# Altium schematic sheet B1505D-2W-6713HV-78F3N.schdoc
size 277 x 190 mm; Device: default297x210; Symbol: default297x210; Name: default297x210; Date: 2025.07.09; Rev: V1.1; Size: "A4"; Id: /; File: B1505D-2W-6713HV-78F3N; Sheet: /; @Page No: 1; @Page Count: 1; @Schematic Name: B1505D-2W-6713HV-78F3N; @Project Name: 全桥隔离电源-B1505D-2W-6713HV-78F3N; @Board Name: B1505D-2W-6713HV-78F3N; @Update Date: 2025-07-09; @Create Time: 17:16:26; @Update Time: 09:23:58; @Page Name: B1505D-2W-6713HV-78F3N; @Create Date: 2025-07-08
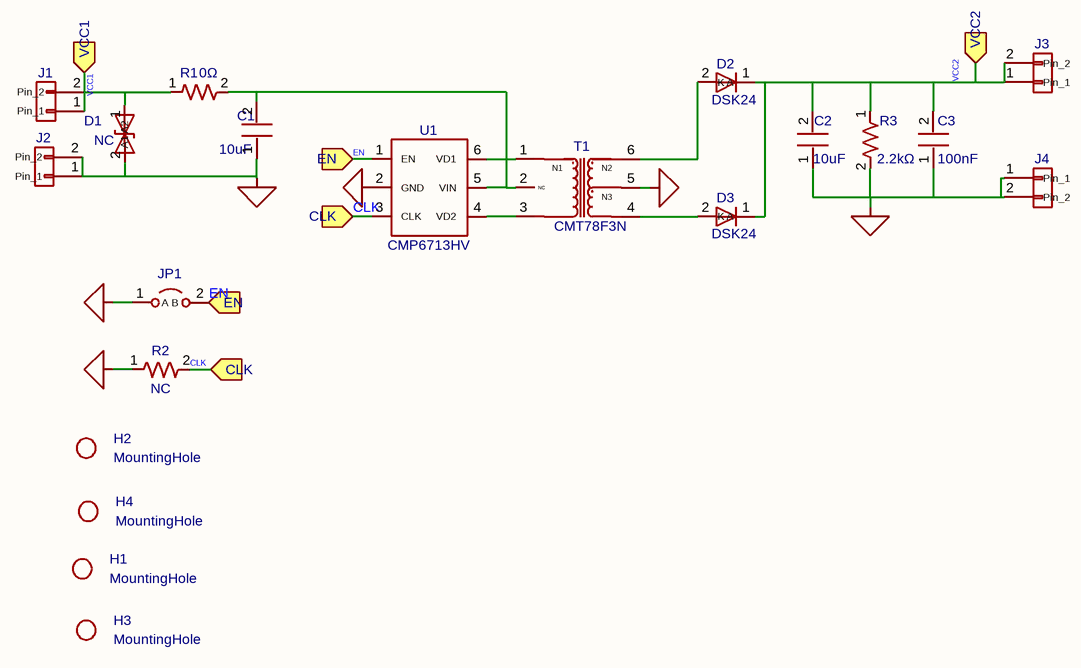
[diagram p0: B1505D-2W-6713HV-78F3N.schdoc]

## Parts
C1  10uF  [C0805]
C2  10uF  [C0805]
C3  100nF  [C0603]
D1  value NC  [SOD-123FL_L2.8-W1.8-LS3.7-BI]
D2  DSK24  [SOD-123_L2.8-W1.8-LS3.7-RD]
D3  DSK24  [SOD-123_L2.8-W1.8-LS3.7-RD]
H1  value MountingHole  [MountingHole:MountingHole_3.2mm_M3]  (hidden comment: Mechanical_MountingHole)
H2  value MountingHole  [MountingHole:MountingHole_3.2mm_M3]  (hidden comment: Mechanical_MountingHole)
H3  value MountingHole  [MountingHole:MountingHole_3.2mm_M3]  (hidden comment: Mechanical_MountingHole)
H4  value MountingHole  [MountingHole:MountingHole_3.2mm_M3]  (hidden comment: Mechanical_MountingHole)
J1  Connector_Generic_Conn_01x02  [Connector_PinHeader_2.54mm:PinHeader_1x02_P2.54mm_Vertical]  (value not drawn)
J2  Connector_Generic_Conn_01x02  [Connector_PinHeader_2.54mm:PinHeader_1x02_P2.54mm_Vertical]  (value not drawn)
J3  Connector_Generic_Conn_01x02  [Connector_PinHeader_2.54mm:PinHeader_1x02_P2.54mm_Vertical]  (value not drawn)
J4  Connector_Generic_Conn_01x02  [Connector_PinHeader_2.54mm:PinHeader_1x02_P2.54mm_Vertical]  (value not drawn)
JP1  Jumper_Jumper_2_Open  [Connector_PinHeader_2.54mm:PinHeader_1x02_P2.54mm_Vertical]  (value not drawn)
R1  0Ω  [R0603]
R2  NC  [R0603]
R3  2.2kΩ  [R0603]
T1  CMT78F3N  [XFMR-SMD_CMT78GFN1]
U1  CMP6713HV  [SOT-23-6_L2.9-W1.6-P0.95-LS2.8-BR]

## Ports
CLK (in), EN (in), VCC1 (in), VCC2 (in)

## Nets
GND1: C1.1 D1.2(A2) J2.1(Pin_1) J2.2(Pin_2) JP1.1(A) R2.1 U1.2(GND)
GND2: C2.1 C3.1 J4.1(Pin_1) J4.2(Pin_2) R3.2 T1.5
CLK: R2.2 U1.3(CLK) ; port CLK
EN: JP1.2(B) U1.1(EN) ; port EN
VCC1: D1.1(A1) J1.1(Pin_1) J1.2(Pin_2) R1.1 ; port VCC1
VCC2: C2.2 C3.2 D2.1(K) D3.1(K) J3.1(Pin_1) J3.2(Pin_2) R3.1 ; port VCC2
NetC1_2: C1.2 R1.2 T1.2 U1.5(VIN)
NetD2_2: D2.2(A) T1.6
NetD3_2: D3.2(A) T1.4
NetT1_1: T1.1 U1.6(VD1)
NetT1_3: T1.3 U1.4(VD2)

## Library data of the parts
C1 = CC0805KKX5R8BB106_C89831: 容值:10uF;精度:±10%;额定电压:25V;材质(温度系数):X5R;; Manufacturer: YAGEO(国巨); Symbol: My_Library_C; AddInBom: yes; ModelId: 1ba041120af144c991958decab20d241; ModelName: C0805_L2.0-W1.3-H1.3; ModelTransform: 78.74,51.181,0,0,0,0,0,0.0005,0; Tolerance: ±10%; Voltage Rated: 25V; Temperature Coefficient: X5R
C2 = CC0805KKX5R6BB106: 容值:10uF;精度:±10%;额定电压:10V;材质(温度系数):X5R;; Manufacturer: YAGEO(国巨); Symbol: My_Library_C; AddInBom: yes; ModelId: 1ba041120af144c991958decab20d241; ModelName: C0805_L2.0-W1.3-H1.3; ModelTransform: 78.74,51.181,0,0,0,0,0,0.0005,0; Tolerance: ±10%; Voltage Rated: 10V; Temperature Coefficient: X5R
C3 = CC0603KRX7R9BB104: 容值:100nF;精度:±10%;额定电压:50V;温度系数:X7R;; Manufacturer: YAGEO(国巨); Symbol: My_Library_C; AddInBom: yes; ModelId: ac125912035d415993ca9572d50418b1; ModelName: C0603_L1.6-W0.8-H0.8; ModelTransform: 62.992,31.496,0,0,0,0,0,0,0; Tolerance: ±10%; Voltage Rating: 50V; Temperature Coefficient: X7R
D1 = SMF28CA_C364280: Symbol: Diode_SMAJ30CA; Add into BOM: no; ConvertToPcb: yes; ModelId: d105299b3871451c86f679efef28ff8f; ModelTransform: 145.669,70.866,0,0,0,0,0,0,0; Type: TVS
D2 D3 = DSK24 K24: 二极管配置:独立式;正向压降(Vf):550mV@2A;直流反向耐压(Vr):40V;整流电流:2A;; Manufacturer: MDD(辰达半导体); Symbol: My_Library_D; Reverse Voltage (Vr): 40V; Rectified Current: 2A; AddInBom: yes; ModelId: 7884390a25fb4c08947731ebfba7e3f8; ModelTransform: 144.8816,62.992,0,0,0,0,0,0,0; Diode Configuration: 独立式; Reverse Leakage Current (Ir): 500uA@40V
H1-H4 = Mechanical_MountingHole: Mounting Hole without connection; Users: REF**; ki_fp_filters: MountingHole*; AddInBom: yes
J1-J4 = Connector_Generic_Conn_01x02: Users: REF**; ki_fp_filters: Jumper* TestPoint*2Pads* TestPoint*Bridge*; AddInBom: yes
JP1 = Jumper_Jumper_2_Open: Jumper, 2-pole, open; AddInBom: yes
R1 = RC0603FR-070RL: 电阻类型:厚膜电阻;阻值:0Ω;精度:±1%;功率:100mW;工作电压:75V;温度系数:-;; Manufacturer: YAGEO(国巨); Symbol: My_Library_R; AddInBom: yes; ModelId: fc143cca1e79419f9cd78b61e9279f08; ModelTransform: 31.8897,63.7794,0,90,0,0,0,0,0; Tolerance: ±1%; Power(Watts): 100mW; Voltage-Supply(Max): 75V
R2 = RC0603FR-0715KL: 电阻类型:厚膜电阻;阻值:15kΩ;精度:±1%;功率:100mW;最大工作电压:75V;温度系数:±100ppm/℃;; Symbol: My_Library_R; Add into BOM: no; ConvertToPcb: yes; ModelId: fc143cca1e79419f9cd78b61e9279f08; ModelTransform: 31.8897,63.7794,0,90,0,0,0,0,0; Tolerance: ±1%
R3 = RC0603FR-072K2L: 电阻类型:厚膜电阻;阻值:2.2kΩ;精度:±1%;功率:100mW;工作电压:75V;温度系数:±100ppm/℃;; Manufacturer: YAGEO(国巨); Symbol: My_Library_R; AddInBom: yes; ModelId: fc143cca1e79419f9cd78b61e9279f08; ModelTransform: 31.8897,63.7794,0,90,0,0,0,0,0; Tolerance: ±1%; Power(Watts): 100mW; Voltage-Supply(Max): 75V
T1 = CMT78F3N: 电源变压器 SMD-6 隔离耐压：2.5KV 一次绕组：单路 二次绕组：双路 功率5W; Manufacturer: coileasy(线易); Symbol: CMT78G4N; AddInBom: yes
U1 = CMP6713HV: CMP6713HV 是全桥式变压器驱动器，芯片内部集成两个 N 型功率 MOSFET 和两个 P 型功率 MOSFET，通过内部振荡器提供具有精准时序和死区时间的互补驱动信号。驱动器搭配配套的变压器，可以实现输入电压6.5V-30V, 输出功率不超过 2W 的隔离电源。采用不同的变压器，外围只需搭配简单的输入输出滤波电容，隔离变压器和整流电路，即可获得多种电压的非稳压输出。产品提供电阻选频功能，可以在 200-420 kHz 范围内连续调整开关频率。; Manufacturer: coileasy(线易); Symbol: MYLibrary_CMP6713RE/HV; AddInBom: yes; ModelId: 18da8f6c14a34920b3e136b5c401a119; ModelName: SOT-23-6_L2.9-W1.6-H1.5-LS2.8-P0.95; ModelTransform: 110.73671,114.173,0,180,0,0,0.001,-0.003,0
